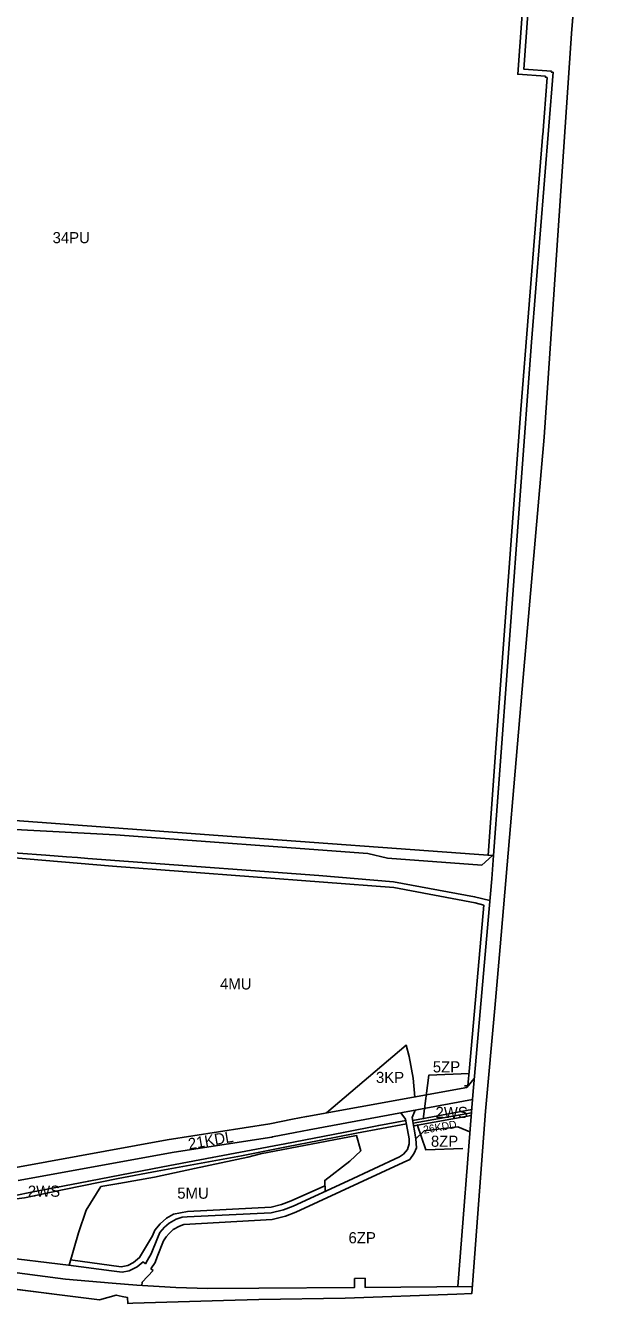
# Model space of a CAD drawing. Extents: x 7428203 to 7432868, y 5542672 to 5545406.
# Drawn here: x 7432333 to 7432841, y 5542811 to 5543958 of the extents above; entities that cross this region are included whole.
import ezdxf

# ---------------------------------------------------------------- set-up
doc = ezdxf.new("R2010")
doc.units = 0
for name, color, linetype in [('granica_planu', 7, 'Continuous'), ('linie_rozgraniczajace', 7, 'Continuous'), ('linie_zabudowy_nieprzekraczalne', 7, 'Continuous'), ('oznaczenia_przeznaczen', 7, 'Continuous')]:
    doc.layers.add(name, color=color, linetype=linetype)

msp = doc.modelspace()

# ---------------------------------------------------------------- linework, layer by layer
at = {"layer": 'granica_planu'}
msp.add_lwpolyline([(7432841.11, 5544172.46), (7432823.11, 5543950.75), (7432798.59, 5543588.3), (7432779.69, 5543372.68), (7432759.28, 5543131.08), (7432754.29, 5543075.97), (7432745.93, 5542983.56), (7432733.82, 5542819.83), (7432720.29, 5542819.22), (7432620.16, 5542815.7), (7432542.45, 5542814.5), (7432510.86, 5542813.53), (7432429.47, 5542811.01), (7432424.82, 5542810.87), (7432424.69, 5542816.18), (7432419.7, 5542817.15), (7432414.54, 5542818.38), (7432399.43, 5542814.22), (7432366.07, 5542818.36), (7432299.15, 5542826.68)], dxfattribs=at)
at = {"layer": 'linie_rozgraniczajace'}
for p, q in [((7432841.11, 5544172.46), (7432823.11, 5543950.75)), ((7432823.11, 5543950.75), (7432798.59, 5543588.3)), ((7432798.59, 5543588.3), (7432779.69, 5543372.68)), ((7432779.69, 5543372.68), (7432759.28, 5543131.08)), ((7432505.88, 5543230.9), (7432224.95, 5543251.39)), ((7432752.27, 5543212.93), (7432505.88, 5543230.9)), ((7432425.58, 5543207.4), (7432388.91, 5543210.14)), ((7432425.58, 5543207.4), (7432596.46, 5543194.88)), ((7432751.54, 5543191.99), (7432753.15, 5543212.94)), ((7432753.15, 5543212.94), (7432752.27, 5543212.93)), ((7432751.54, 5543191.99), (7432749.23, 5543165.16)), ((7432749.23, 5543165.16), (7432734.6, 5542997.86)), ((7432759.28, 5543131.08), (7432754.29, 5543075.97)), ((7432754.29, 5543075.97), (7432745.93, 5542983.56)), ((7432735.9, 5543012.75), (7432729.26, 5543004.57)), ((7432585.54, 5542978.64), (7432729.26, 5543004.57)), ((7432587.68, 5542966.83), (7432734.29, 5542993.87)), ((7432734.6, 5542997.86), (7432721.09, 5542825.95)), ((7432572.73, 5542976.14), (7432585.29, 5542978.59)), ((7432674.33, 5542976.12), (7432670.13, 5542982.04)), ((7432680.24, 5542977.81), (7432682.93, 5542984.4)), ((7432680.24, 5542977.81), (7432683.46, 5542958.56)), ((7432680.7, 5542975.09), (7432733.59, 5542985.05)), ((7432681.08, 5542972.81), (7432733.36, 5542982.05)), ((7432733.15, 5542979.42), (7432681.52, 5542970.15)), ((7432745.93, 5542983.56), (7432733.82, 5542819.83)), ((7432575.03, 5542964.36), (7432587.59, 5542966.82)), ((7432674.33, 5542976.12), (7432677.38, 5542958.52)), ((7432466.38, 5542946.5), (7432554.28, 5542960.24)), ((7432554.28, 5542960.24), (7432554.78, 5542960.32)), ((7432554.78, 5542960.32), (7432575.01, 5542964.36)), ((7432575.01, 5542964.36), (7432575.03, 5542964.36)), ((7432677.38, 5542958.52), (7432677.41, 5542954.21)), ((7432690.91, 5542965.8), (7432683.46, 5542958.56)), ((7432683.46, 5542958.56), (7432683.95, 5542950.67)), ((7432466.38, 5542946.5), (7432326.44, 5542921.16)), ((7432672.49, 5542944.97), (7432668.87, 5542942.34)), ((7432675.87, 5542948.98), (7432672.49, 5542944.97)), ((7432677.41, 5542954.21), (7432675.87, 5542948.98)), ((7432682, 5542945.63), (7432677.94, 5542940.13)), ((7432683.95, 5542950.67), (7432682, 5542945.63)), ((7432672.12, 5542937.23), (7432575.61, 5542892.75)), ((7432668.87, 5542942.34), (7432622.58, 5542921)), ((7432677.94, 5542940.13), (7432672.12, 5542937.23)), ((7432622.58, 5542921), (7432573.28, 5542898.28)), ((7432573.28, 5542898.28), (7432564.68, 5542895)), ((7432468.33, 5542886.55), (7432462.07, 5542883)), ((7432473.65, 5542888.25), (7432468.33, 5542886.55)), ((7432478.33, 5542888.48), (7432473.65, 5542888.25)), ((7432554.6, 5542886.21), (7432475.06, 5542881.71)), ((7432553.69, 5542892.17), (7432478.33, 5542888.48)), ((7432564.68, 5542895), (7432553.69, 5542892.17)), ((7432566.51, 5542889.27), (7432554.6, 5542886.21)), ((7432575.61, 5542892.75), (7432566.51, 5542889.27)), ((7432453.73, 5542874.46), (7432451.47, 5542869.52)), ((7432457.73, 5542879.28), (7432453.73, 5542874.46)), ((7432462.07, 5542883), (7432457.73, 5542879.28)), ((7432465.57, 5542877.18), (7432461.88, 5542873.79)), ((7432471.15, 5542880.29), (7432465.57, 5542877.18)), ((7432475.06, 5542881.71), (7432471.15, 5542880.29)), ((7432451.47, 5542869.52), (7432445.86, 5542855.3)), ((7432456.99, 5542867.16), (7432451.28, 5542852.7)), ((7432459.31, 5542870.55), (7432456.99, 5542867.16)), ((7432461.88, 5542873.79), (7432459.31, 5542870.55)), ((7432371.53, 5542845.19), (7432259.18, 5542859.04)), ((7432445.86, 5542855.3), (7432442.72, 5542849.83)), ((7432451.28, 5542852.7), (7432449.31, 5542847.51)), ((7432368.86, 5542832.71), (7432253.01, 5542848.01)), ((7432410.31, 5542840.07), (7432371.53, 5542845.19)), ((7432419.86, 5542838.89), (7432410.31, 5542840.07)), ((7432425.98, 5542840.08), (7432419.86, 5542838.89)), ((7432433.37, 5542843.71), (7432425.98, 5542840.08)), ((7432438.68, 5542848.24), (7432433.37, 5542843.71)), ((7432447.73, 5542840.29), (7432437.66, 5542829.89)), ((7432440.78, 5542846.42), (7432438.68, 5542848.24)), ((7432442.72, 5542849.83), (7432440.78, 5542846.42)), ((7432449.31, 5542847.51), (7432445.63, 5542841.84)), ((7432445.63, 5542841.84), (7432447.73, 5542840.29)), ((7432410.83, 5542828.97), (7432368.86, 5542832.71)), ((7432433.03, 5542827.27), (7432410.83, 5542828.97)), ((7432437.66, 5542829.89), (7432437.52, 5542826.99)), ((7432366.07, 5542818.36), (7432299.15, 5542826.68)), ((7432399.43, 5542814.22), (7432366.07, 5542818.36)), ((7432414.54, 5542818.38), (7432399.43, 5542814.22)), ((7432419.7, 5542817.15), (7432414.54, 5542818.38)), ((7432424.69, 5542816.18), (7432419.7, 5542817.15)), ((7432720.29, 5542819.22), (7432620.16, 5542815.7)), ((7432733.82, 5542819.83), (7432720.29, 5542819.22)), ((7432424.82, 5542810.87), (7432424.69, 5542816.18)), ((7432429.47, 5542811.01), (7432424.82, 5542810.87)), ((7432510.86, 5542813.53), (7432429.47, 5542811.01)), ((7432542.45, 5542814.5), (7432510.86, 5542813.53)), ((7432620.16, 5542815.7), (7432542.45, 5542814.5))]:
    msp.add_line(p, q, dxfattribs=at)
for points in [[(7432802.65, 5544225.29), (7432780.32, 5543918.74), (7432805.14, 5543917.02), (7432805.06, 5543916.02), (7432806.7, 5543915.91), (7432787.32, 5543673.69), (7432757.78, 5543273.24), (7432753.15, 5543212.94)], [(7432049.82, 5543256.21), (7432136.37, 5543244.64), (7432186.04, 5543244.35), (7432216.24, 5543242.02), (7432413.94, 5543231.48), (7432640.36, 5543214.85), (7432658.04, 5543210.49), (7432742.56, 5543204.3), (7432752.27, 5543212.93)], [(7432388.91, 5543210.14), (7432379.65, 5543211.02), (7432369.94, 5543211.73), (7432351.23, 5543213.11), (7432301.34, 5543216.75), (7432174.33, 5543226.52), (7432071.7, 5543238.19)], [(7432749.86, 5543172.45), (7432736.14, 5543175.85), (7432663.43, 5543189.23), (7432596.46, 5543194.88)], [(7432682.47, 5542996.13), (7432681.08, 5543013.06), (7432677.4, 5543032.38), (7432674.85, 5543042.61), (7432603.13, 5542981.81)], [(7432184.35, 5542881.75), (7432235.29, 5542890.99), (7432294.29, 5542901.7), (7432338.45, 5542910.71), (7432389.9, 5542920.66), (7432456.41, 5542933.52), (7432500.71, 5542941.8), (7432565.92, 5542953.99), (7432618.41, 5542964.35), (7432650.2, 5542970.62), (7432674.54, 5542974.93)], [(7432675.05, 5542971.98), (7432630.33, 5542963.79), (7432596.76, 5542957.17), (7432567.37, 5542951.38), (7432527, 5542943.43), (7432451.25, 5542929.57), (7432416.09, 5542923.14)], [(7432460.08, 5542957.66), (7432552.43, 5542972.09), (7432572.66, 5542976.13)], [(7432690.91, 5542965.8), (7432721.25, 5542969.48), (7432732, 5542964.8)], [(7432460.08, 5542957.66), (7432324.29, 5542932.96), (7432250.93, 5542919.95)], [(7432601.92, 5542911.48), (7432601.7, 5542921.31), (7432624.24, 5542938.69), (7432633.96, 5542947.91), (7432630.2, 5542961.51), (7432544.01, 5542945.15), (7432532.68, 5542942.05), (7432484.63, 5542932.03), (7432448.77, 5542924.09), (7432416.81, 5542918.64), (7432400.82, 5542915.71), (7432387.59, 5542894.53), (7432380.51, 5542874.27), (7432372.23, 5542845.09)], [(7432416.09, 5542923.14), (7432367.66, 5542913.04), (7432332.08, 5542905.7), (7432320.15, 5542904.09), (7432300.61, 5542900.16), (7432244.28, 5542890.06), (7432184.93, 5542878.81)], [(7432433.03, 5542827.27), (7432467.89, 5542825.08), (7432496.6, 5542824.35), (7432542.66, 5542824.45), (7432628.52, 5542825.23), (7432628.53, 5542833.16), (7432637.97, 5542833.46), (7432637.88, 5542825.19), (7432734.28, 5542826.07)]]:
    msp.add_lwpolyline(points, dxfattribs=at)
for centre, radius, start, end in [((7432585.82, 5542976.59), 2.069, 97.7776379, 104.8422271), ((7432572.68, 5542976.24), 0.1118, 259.6951535, 296.5650512), ((7432587.61, 5542967.05), 0.2309, 265.0302593, 287.6501242)]:
    msp.add_arc(centre, radius, start, end, dxfattribs=at)
at = {"layer": 'linie_zabudowy_nieprzekraczalne'}
for points in [[(7432797.46, 5543859.74), (7432801.34, 5543911.17), (7432799.79, 5543911.36), (7432799.75, 5543912.38), (7432774.97, 5543914.1), (7432780.43, 5543989.03)], [(7432748.49, 5543213.21), (7432755.72, 5543313.3), (7432777.84, 5543613.15), (7432791.52, 5543786.8), (7432797.37, 5543861.08)], [(7432411.3, 5543203.48), (7432319.63, 5543211.15), (7432310.08, 5543203.33), (7432305.74, 5543061.76), (7432181.54, 5543067.1)], [(7432744.49, 5543168.42), (7432736.81, 5543170.53), (7432663.56, 5543184.12), (7432411.23, 5543203.47), (7432411.23, 5543203.47)], [(7432727.03, 5543006.2), (7432730.26, 5543006.08), (7432731.54, 5543022.43), (7432744.49, 5543168.42)], [(7432373.3, 5542850), (7432418.9, 5542843.8), (7432425.03, 5542844.99), (7432430.12, 5542847.51), (7432435.43, 5542852.05), (7432446.92, 5542871.6), (7432449.19, 5542876.54), (7432453.89, 5542882.47), (7432459.61, 5542887.35), (7432465.86, 5542890.9), (7432478.54, 5542893.49), (7432553.45, 5542897.17), (7432562.9, 5542899.67), (7432571.49, 5542902.95), (7432601.81, 5542916.53)]]:
    msp.add_lwpolyline(points, dxfattribs=at)
at = {"layer": 'oznaczenia_przeznaczen'}
for points in [[(7432731.44, 5543017.3), (7432695.25, 5543015.83), (7432690.16, 5542976.16)], [(7432725.7, 5542949.94), (7432692.57, 5542948.63), (7432684.8, 5542971.45)]]:
    msp.add_lwpolyline(points, dxfattribs=at)

# ---------------------------------------------------------------- texts
for s, p in [('34PU', (7432357.3728, 5543762.47)), ('4MU', (7432507.6964, 5543092.67)), ('5ZP', (7432698.729, 5543018.23)), ('3KP', (7432647.6742, 5543008.74)), ('2WS', (7432701.1559, 5542977.32)), ('8ZP', (7432696.989, 5542951.47)), ('2WS', (7432335.1559, 5542906.63)), ('5MU', (7432469.3064, 5542904.85)), ('6ZP', (7432623.049, 5542864.85))]:
    msp.add_text(s, height=10, dxfattribs=at).set_placement(p)
for s, height, rotation, p in [('26KDD', 7, 10.071822, (7432690.7943, 5542963.1551)), ('21KDL', 10, 9.876011, (7432479.9859, 5542948.9471))]:
    msp.add_text(s, height=height, rotation=rotation, dxfattribs=at).set_placement(p)

doc.saveas('drawing.dxf')
